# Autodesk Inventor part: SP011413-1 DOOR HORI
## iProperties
Company: MiniTec Framing Systems, LLC
Created: 2013-01
Part Number: SP011413-1 DOOR HORI
Material: Aluminum-6061
Description: PROFILE 19X45
Document SubType Name: Modeling
Designer: Administrator
Stock Number: 20.1001 PROFILE 19X45
Density: 2.71 g/cm^3
Mass: 912.972 g
Surface Area: 1826.49 cm^2
Volume: 336.89 cm^3
FINISH: CLEAR ANODIZED
Author: Administrator
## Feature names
1. Extrusion1
